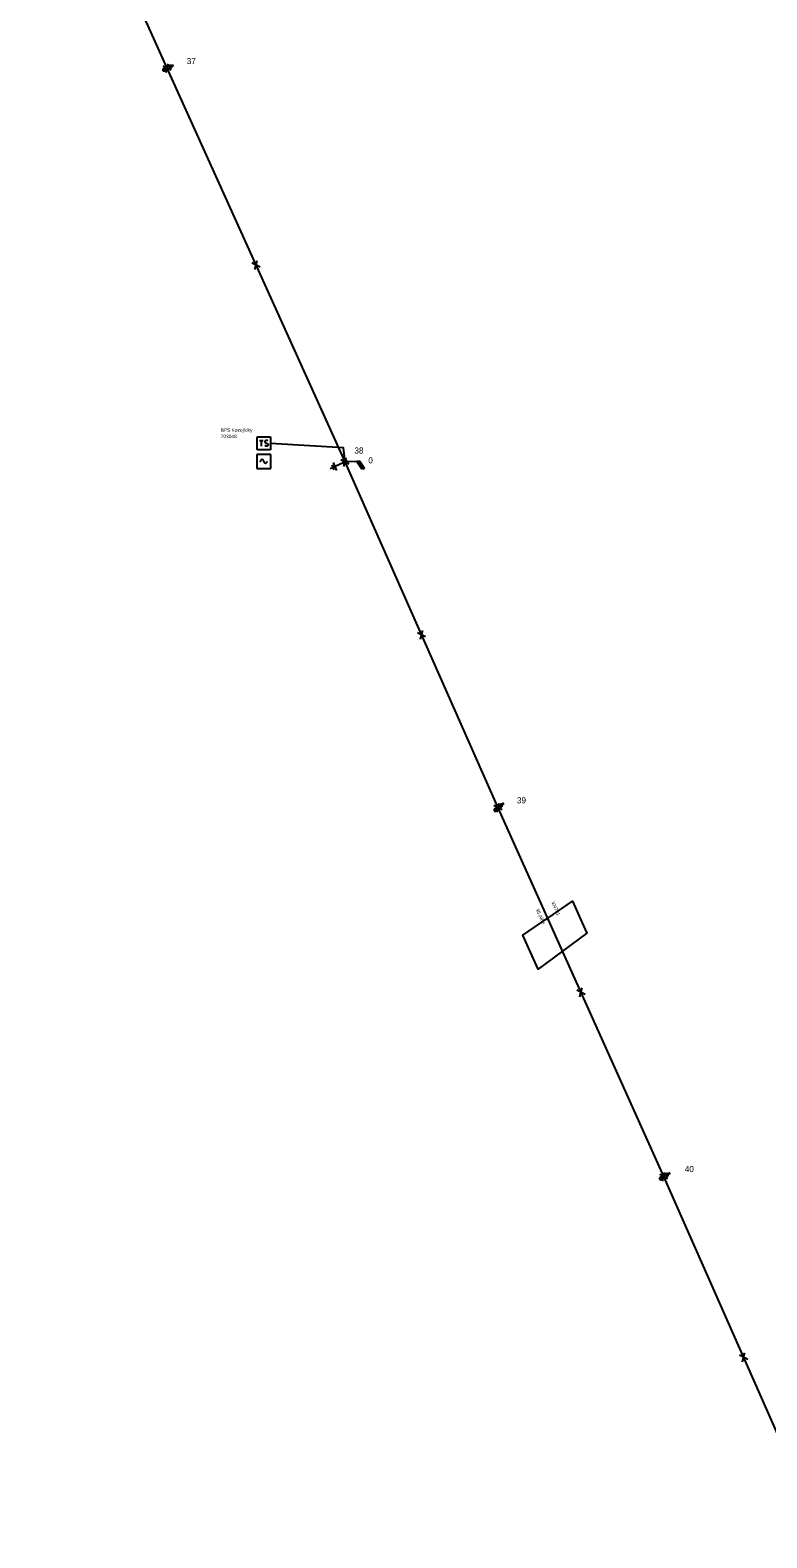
# Model space of a CAD drawing. Extents: x -544790 to -541580, y -1198998 to -1195432.
# Drawn here: x -543529 to -543317.4, y -1198165.2 to -1197732.2 of the extents above; entities that cross this region are included whole.
import ezdxf

# ---------------------------------------------------------------- set-up
doc = ezdxf.new("R2010")
doc.units = 0
for name, color, linetype in [('DOPLŇ_POPISY', 7, 'Continuous'), ('ELE_EON', 7, 'Continuous'), ('ELE_EON_POPIS', 7, 'Continuous'), ('Implicitní', 7, 'Continuous'), ('KN_HRAN_K_Ú', 7, 'Continuous'), ('KN_HRAN_KRAJSKÁ', 7, 'Continuous'), ('KN_PARC_Č', 7, 'Continuous'), ('KN_VKP_HRAN_NEZNATELNÁ', 7, 'Continuous'), ('KONEC_VEDENÍ', 7, 'Continuous'), ('PK_HRAN_SPORNÁ', 7, 'Continuous'), ('PLG_EXPORT_GPE', 7, 'Continuous'), ('PROJEKT', 7, 'Continuous'), ('RÁMEČEK', 7, 'Continuous'), ('SDEL_EON', 7, 'Continuous'), ('TECH_OCHR_PÁSMO_HRAN', 7, 'Continuous'), ('UZEM_PŮDORYS_NN', 7, 'Continuous'), ('ZRUŠENO', 7, 'Continuous')]:
    doc.layers.add(name, color=color, linetype=linetype)

# ---------------------------------------------------------------- blocks, each defined once
blk = doc.blocks.new('VN435')
at = {"layer": 'ELE_EON_POPIS'}
for points in [[(-2.06, 0.66), (-2.13, 0.65), (-2.2, 0.64), (-2.27, 0.62), (-2.34, 0.6), (-2.4, 0.56), (-2.47, 0.52), (-2.52, 0.48), (-2.57, 0.43), (-2.62, 0.37), (-2.66, 0.31), (-2.69, 0.24), (-2.72, 0.17), (-2.74, 0.1), (-2.75, 0.03), (-2.75, -0.04), (-2.75, -0.11), (-2.74, -0.19), (-2.72, -0.26), (-2.69, -0.32), (-2.66, -0.39), (-2.62, -0.45), (-2.57, -0.51), (-2.52, -0.56), (-2.47, -0.61), (-2.4, -0.65), (-2.34, -0.68), (-2.27, -0.7), (-2.2, -0.72), (-2.13, -0.74), (-2.06, -0.74), (-1.98, -0.74), (-1.91, -0.72), (-1.84, -0.7), (-1.77, -0.68), (-1.71, -0.65), (-1.65, -0.61), (-1.59, -0.56), (-1.54, -0.51), (-1.49, -0.45), (-1.45, -0.39), (-1.42, -0.32), (-1.39, -0.26), (-1.37, -0.19), (-1.36, -0.11), (-1.36, -0.04), (-1.36, 0.03), (-1.37, 0.1), (-1.39, 0.17), (-1.42, 0.24), (-1.45, 0.31), (-1.49, 0.37), (-1.54, 0.43), (-1.59, 0.48), (-1.65, 0.52), (-1.71, 0.56), (-1.77, 0.6), (-1.84, 0.62), (-1.91, 0.64), (-1.98, 0.65), (-2.06, 0.66)], [(-2.06, 0.66), (-2.06, -0.74)], [(-2.06, 0.66), (2.18, 0.66)], [(2.18, 0.66), (2.1, 0.65), (2.03, 0.64), (1.96, 0.62), (1.89, 0.6), (1.83, 0.56), (1.77, 0.52), (1.71, 0.48), (1.66, 0.43), (1.61, 0.37), (1.57, 0.31), (1.54, 0.24), (1.51, 0.17), (1.49, 0.1), (1.48, 0.03), (1.48, -0.04), (1.48, -0.11), (1.49, -0.19), (1.51, -0.26), (1.54, -0.32), (1.57, -0.39), (1.61, -0.45), (1.66, -0.51), (1.71, -0.56), (1.77, -0.61), (1.83, -0.65), (1.89, -0.68), (1.96, -0.7), (2.03, -0.72), (2.1, -0.74), (2.18, -0.74), (2.25, -0.74), (2.32, -0.72), (2.39, -0.7), (2.46, -0.68), (2.53, -0.65), (2.59, -0.61), (2.64, -0.56), (2.7, -0.51), (2.74, -0.45), (2.78, -0.39), (2.82, -0.32), (2.84, -0.26), (2.86, -0.19), (2.87, -0.11), (2.88, -0.04), (2.87, 0.03), (2.86, 0.1), (2.84, 0.17), (2.82, 0.24), (2.78, 0.31), (2.74, 0.37), (2.7, 0.43), (2.64, 0.48), (2.59, 0.52), (2.53, 0.56), (2.46, 0.6), (2.39, 0.62), (2.32, 0.64), (2.25, 0.65), (2.18, 0.66)], [(2.18, 0.66), (2.18, -0.74)], [(3.68, -0.76), (3.68, 0.65)], [(-2.75, -0.04), (-1.36, -0.04)], [(-2.06, -0.74), (2.18, -0.74)], [(1.48, -0.04), (2.88, -0.04)]]:
    blk.add_lwpolyline(points, dxfattribs=at)
blk = doc.blocks.new('VN810')
at = {"layer": 'PLG_EXPORT_GPE'}
for points in [[(1.25, -3.75), (-1.25, -3.75)], [(0, -1.25), (0, -3.75)], [(0.77, -4.37), (-0.8, -4.37)], [(0, -5), (-0.25, -5)], [(0.27, -5), (0, -5)]]:
    blk.add_lwpolyline(points, dxfattribs=at)
blk = doc.blocks.new('VN740')
at = {"layer": 'ELE_EON'}
for points in [[(2, 2), (-2, 2)], [(-2, 2), (-2, -2)], [(0, 0), (0, 0.05), (-0.01, 0.1), (-0.02, 0.15), (-0.04, 0.2), (-0.06, 0.24), (-0.09, 0.29), (-0.12, 0.33), (-0.16, 0.36), (-0.2, 0.4), (-0.24, 0.42), (-0.29, 0.45), (-0.34, 0.47), (-0.38, 0.48), (-0.44, 0.49), (-0.49, 0.49), (-0.54, 0.49), (-0.59, 0.48), (-0.64, 0.47), (-0.69, 0.45), (-0.73, 0.43), (-0.77, 0.4), (-0.81, 0.37), (-0.85, 0.33), (-0.88, 0.29), (-0.91, 0.25), (-0.93, 0.2), (-0.95, 0.16), (-0.97, 0.11), (-0.97, 0.06), (-0.98, 0), (-0.98, 0)], [(2, -2), (2, 2)], [(-2, -2), (2, -2)], [(0, 0), (0, -0.05), (0.01, -0.1), (0.02, -0.15), (0.04, -0.2), (0.06, -0.24), (0.09, -0.28), (0.12, -0.32), (0.15, -0.36), (0.19, -0.39), (0.23, -0.42), (0.28, -0.44), (0.32, -0.46), (0.37, -0.48), (0.42, -0.49), (0.47, -0.49), (0.52, -0.49), (0.57, -0.48), (0.62, -0.47), (0.67, -0.45), (0.71, -0.43), (0.75, -0.4), (0.79, -0.37), (0.83, -0.34), (0.86, -0.3), (0.89, -0.26), (0.91, -0.21), (0.93, -0.17), (0.95, -0.12), (0.96, -0.07), (0.96, -0.02), (0.96, -0.02)]]:
    blk.add_lwpolyline(points, dxfattribs=at)
blk = doc.blocks.new('VN640')
at = {"layer": 'ZRUŠENO'}
for points in [[(-1.89, 1.89), (1.89, 1.89)], [(-1.89, -1.89), (-1.89, 1.89)], [(-1.26, 0.79), (-0.22, 0.79)], [(-0.73, 0.79), (-0.73, -0.79)], [(1.2, 0.66), (0.94, 0.79), (0.66, 0.79), (0.41, 0.66), (0.28, 0.47), (0.28, 0.41), (0.41, 0.22), (1.13, -0.16), (1.26, -0.32), (1.26, -0.47), (1.13, -0.66), (0.91, -0.79), (0.63, -0.79), (0.5, -0.73), (0.28, -0.6)], [(1.89, 1.89), (1.89, -1.89)], [(1.89, -1.89), (-1.89, -1.89)]]:
    blk.add_lwpolyline(points, dxfattribs=at)
blk = doc.blocks.new('VN001')
at = {"layer": 'Implicitní'}
for p, q in [((1.73, 3.03), (4.14, 3.03)), ((1.76, 3.08), (4.17, 3.08)), ((1.79, 3.13), (4.2, 3.13)), ((1.82, 3.18), (4.23, 3.18)), ((1.85, 3.23), (4.26, 3.23)), ((1.87, 3.28), (4.29, 3.28)), ((1.9, 3.33), (4.32, 3.33)), ((1.93, 3.38), (4.35, 3.38)), ((1.96, 3.43), (4.37, 3.43)), ((1.99, 3.48), (4.4, 3.48)), ((2.02, 3.53), (4.43, 3.53)), ((2.05, 3.58), (4.46, 3.58)), ((2.07, 3.63), (4.49, 3.63)), ((2.1, 3.68), (4.52, 3.68)), ((2.13, 3.73), (2.54, 3.73))]:
    blk.add_line(p, q, dxfattribs=at)
blk.add_lwpolyline([(2.13, 3.73), (0, 0)], dxfattribs=at)
blk.add_lwpolyline([(4.55, 3.73), (2.13, 3.73), (1.7, 2.98), (4.12, 2.99)], close=True, dxfattribs=at)
blk = doc.blocks.new('VN440')
at = {"layer": 'ELE_EON_POPIS'}
for points in [[(1.22, 0), (1.21, 0.13), (1.19, 0.25), (1.16, 0.38), (1.11, 0.5), (1.05, 0.61), (0.98, 0.72), (0.9, 0.82), (0.81, 0.91), (0.71, 0.99), (0.6, 1.06), (0.49, 1.12), (0.37, 1.16), (0.25, 1.2), (0.12, 1.22), (-0.01, 1.22), (-0.14, 1.22), (-0.26, 1.2), (-0.39, 1.16), (-0.51, 1.12), (-0.62, 1.06), (-0.73, 0.99), (-0.83, 0.91), (-0.92, 0.82), (-1, 0.72), (-1.07, 0.61), (-1.13, 0.5), (-1.18, 0.38), (-1.21, 0.25), (-1.23, 0.13), (-1.24, 0), (-1.23, -0.13), (-1.21, -0.26), (-1.18, -0.38), (-1.13, -0.5), (-1.07, -0.62), (-1, -0.73), (-0.92, -0.83), (-0.83, -0.92), (-0.73, -1), (-0.62, -1.07), (-0.51, -1.13), (-0.39, -1.17), (-0.26, -1.2), (-0.14, -1.23), (-0.01, -1.23), (0.12, -1.23), (0.25, -1.2), (0.37, -1.17), (0.49, -1.13), (0.6, -1.07), (0.71, -1), (0.81, -0.92), (0.9, -0.83), (0.98, -0.73), (1.05, -0.62), (1.11, -0.5), (1.16, -0.38), (1.19, -0.26), (1.21, -0.13), (1.22, 0)], [(-1.24, 0), (1.22, 0)], [(-1.18, -0.34), (1.1, -0.34)], [(-1.01, -0.63), (0.97, -0.63)], [(-0.74, -0.92), (0.68, -0.92)]]:
    blk.add_lwpolyline(points, dxfattribs=at)

msp = doc.modelspace()

# ---------------------------------------------------------------- linework, layer by layer
at = {"layer": 'ELE_EON'}
for points in [[(-543438.57, -1197856.18), (-543489.66, -1197743.09), (-543529.03, -1197655.47)], [(-543301.15, -1198165.16), (-543347, -1198061.43), (-543394.61, -1197955.5), (-543438.57, -1197856.18)]]:
    msp.add_lwpolyline(points, dxfattribs=at)
at = {"layer": 'PK_HRAN_SPORNÁ'}
msp.add_lwpolyline([(-543380.77, -1197987.5), (-543380.33, -1197987.2), (-543373.19, -1197982.36), (-543370.88, -1197987.5), (-543369.07, -1197991.52), (-543376.07, -1197996.67), (-543383.08, -1198001.81), (-543387.47, -1197992.05)], close=True, dxfattribs=at)
at = {"layer": 'PROJEKT'}
msp.add_lwpolyline([(-543438.57, -1197856.18), (-543438.98, -1197852.12), (-543460.02, -1197850.85)], dxfattribs=at)
at = {"layer": 'UZEM_PŮDORYS_NN'}
for points in [[(-543488.48, -1197743.7), (-543489.66, -1197743.09), (-543490.84, -1197742.48)], [(-543490, -1197744.37), (-543489.66, -1197743.09), (-543489.32, -1197741.81)], [(-543462.94, -1197800.25), (-543464.12, -1197799.63), (-543465.29, -1197799.02)], [(-543464.45, -1197800.92), (-543464.12, -1197799.63), (-543463.78, -1197798.35)], [(-543437.39, -1197856.79), (-543438.57, -1197856.18), (-543439.75, -1197855.57)], [(-543438.91, -1197857.46), (-543438.57, -1197856.18), (-543438.23, -1197854.9)], [(-543415.41, -1197906.45), (-543416.59, -1197905.84), (-543417.77, -1197905.23)], [(-543416.93, -1197907.12), (-543416.59, -1197905.84), (-543416.25, -1197904.56)], [(-543393.43, -1197956.11), (-543394.61, -1197955.5), (-543395.79, -1197954.89)], [(-543394.95, -1197956.78), (-543394.61, -1197955.5), (-543394.27, -1197954.22)], [(-543369.63, -1198009.08), (-543370.81, -1198008.46), (-543371.98, -1198007.85)], [(-543371.14, -1198009.75), (-543370.81, -1198008.46), (-543370.47, -1198007.18)], [(-543345.82, -1198062.04), (-543347, -1198061.43), (-543348.18, -1198060.82)], [(-543347.34, -1198062.71), (-543347, -1198061.43), (-543346.66, -1198060.15)], [(-543322.9, -1198113.91), (-543324.08, -1198113.29), (-543325.25, -1198112.68)], [(-543324.41, -1198114.58), (-543324.08, -1198113.29), (-543323.74, -1198112.01)]]:
    msp.add_lwpolyline(points, dxfattribs=at)

# ---------------------------------------------------------------- block references
at = {"layer": 'DOPLŇ_POPISY'}
for name, p, xscale, yscale, rotation in [('VN435', (-543489.66, -1197743.09), 0.5, 0.49999999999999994, 25.091102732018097), ('VN440', (-543438.57, -1197856.18), 0.5, 0.5, -65.79214165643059), ('VN435', (-543394.61, -1197955.5), 0.5000000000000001, 0.5000000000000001, 37.309690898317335), ('VN435', (-543347, -1198061.43), 0.5000000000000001, 0.5, 29.89867773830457)]:
    msp.add_blockref(name, p, dxfattribs=dict(at, xscale=xscale, yscale=yscale, rotation=rotation))
at = {"layer": 'KN_HRAN_KRAJSKÁ'}
msp.add_blockref('VN640', (-543461.91, -1197850.82), dxfattribs=at)
at = {"layer": 'KN_VKP_HRAN_NEZNATELNÁ'}
msp.add_blockref('VN740', (-543461.93, -1197856.02), dxfattribs=at)
at = {"layer": 'RÁMEČEK', "rotation": -65.79214165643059}
msp.add_blockref('VN810', (-543437.99, -1197855.92), dxfattribs=at)
at = {"layer": 'TECH_OCHR_PÁSMO_HRAN', "rotation": -58.20922335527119}
msp.add_blockref('VN001', (-543438.57, -1197856.18), dxfattribs=at)

# ---------------------------------------------------------------- texts
at = {"layer": 'ELE_EON_POPIS'}
msp.add_text('95 AlFe', height=1, rotation=294.214, dxfattribs=at).set_placement((-543383.83, -1197984.77))
at = {"layer": 'KN_HRAN_K_Ú'}
msp.add_text('703048', height=1, dxfattribs=at).set_placement((-543474.29, -1197849.34))
at = {"layer": 'KN_PARC_Č'}
msp.add_text('BPS Kozojídky', height=1, dxfattribs=at).set_placement((-543474.31, -1197847.53))
at = {"layer": 'KONEC_VEDENÍ'}
msp.add_text('0', height=1.75, dxfattribs=at).set_placement((-543431.87, -1197856.6))
at = {"layer": 'PLG_EXPORT_GPE'}
for s, p in [('37', (-543484.03, -1197741.93)), ('38', (-543435.88, -1197853.78)), ('39', (-543389.19, -1197954.24)), ('40', (-543340.97, -1198060.12))]:
    msp.add_text(s, height=1.75, dxfattribs=at).set_placement(p)
at = {"layer": 'SDEL_EON'}
msp.add_text('VN701', height=1, rotation=294.214, dxfattribs=at).set_placement((-543379.34, -1197982.72))

doc.saveas('drawing.dxf')
